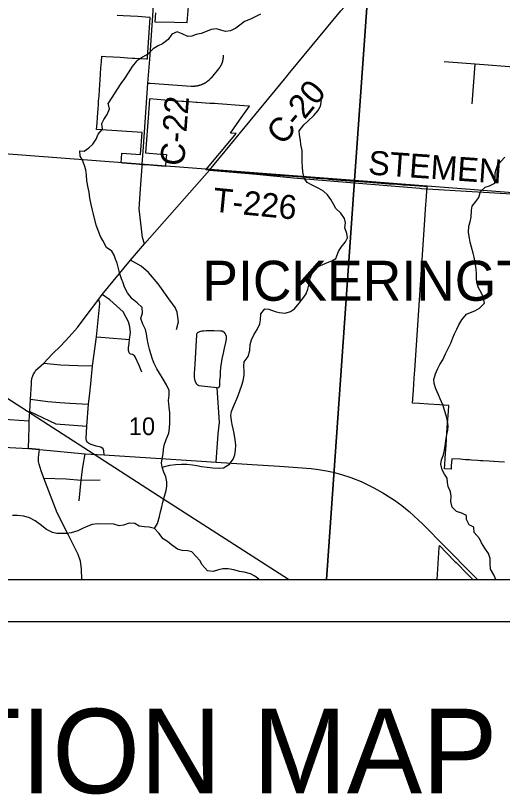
# Model space of a CAD drawing. Extents: x 0 to 34, y 0 to 22.
# Drawn here: x 5.306 to 6.46, y 13.591 to 15.435 of the extents above; entities that cross this region are included whole.
import ezdxf

# ---------------------------------------------------------------- set-up
doc = ezdxf.new("R2010")
doc.units = 0
for name, color, linetype in [('GM_X_City_Street', 7, 'Continuous'), ('GM_X_Corporation', 7, 'Continuous'), ('GM_X_Corporation_Text', 7, 'Continuous'), ('GM_X_County_Road', 7, 'Continuous'), ('GM_X_County_Road_Text', 7, 'Continuous'), ('GM_X_Minor_River', 7, 'Continuous'), ('GM_X_Rail_Line', 7, 'Continuous'), ('GM_X_Section_Text', 7, 'Continuous'), ('GM_X_State_Route', 7, 'Continuous'), ('GM_X_Township_Road', 7, 'Continuous'), ('GM_X_Township_Road_Text', 7, 'Continuous'), ('SH_Data', 7, 'Continuous'), ('SH_Text', 7, 'Continuous')]:
    doc.layers.add(name, color=color, linetype=linetype)

msp = doc.modelspace()

# ---------------------------------------------------------------- linework, layer by layer
at = {"layer": 'GM_X_City_Street'}
msp.add_line((5.4618, 14.3352), (5.5062, 14.3355), dxfattribs=at)
for points in [[(5.6875, 14.6913), (5.6924, 14.7099), (5.6893, 14.7327), (5.6844, 14.7439), (5.6689, 14.7643), (5.6442, 14.7995), (5.6207, 14.8267), (5.6034, 14.8416), (5.5786, 14.8558)], [(5.4819, 14.5408), (5.4842, 14.563), (5.4887, 14.6054), (5.4977, 14.6741), (5.5058, 14.7528), (5.5035, 14.7636)], [(5.7839, 14.5532), (5.7619, 14.5559), (5.7402, 14.5582), (5.7357, 14.5613), (5.7319, 14.5704), (5.73, 14.578), (5.73, 14.5878), (5.732, 14.6099), (5.7348, 14.6656), (5.7356, 14.6774), (5.736, 14.6808), (5.7364, 14.6831)], [(5.8009, 14.6848), (5.7998, 14.6852), (5.796, 14.6875), (5.7918, 14.6879), (5.777, 14.6883), (5.758, 14.6883), (5.7519, 14.688), (5.7474, 14.6876), (5.7443, 14.6872), (5.7417, 14.6865), (5.739, 14.6846), (5.7364, 14.6831)], [(5.7817, 14.3775), (5.7859, 14.4445), (5.7896, 14.4715), (5.7839, 14.5532), (5.7877, 14.5543), (5.7888, 14.555), (5.79, 14.5592), (5.7904, 14.5706), (5.7916, 14.5808), (5.792, 14.5899), (5.7924, 14.6021), (5.7939, 14.6112), (5.7955, 14.6218), (5.7985, 14.6358), (5.8012, 14.6472), (5.8047, 14.6609), (5.8058, 14.6685), (5.8059, 14.6749), (5.8044, 14.6787), (5.8025, 14.6818), (5.8009, 14.6848)], [(5.3727, 14.612), (5.4122, 14.608), (5.4537, 14.6063), (5.4887, 14.6054)], [(5.479, 14.4229), (5.4766, 14.4246), (5.4741, 14.4284), (5.4735, 14.4337), (5.4753, 14.4628), (5.4791, 14.5146), (5.4819, 14.5408)], [(5.3418, 14.5264), (5.3829, 14.5215), (5.4106, 14.5191)], [(5.4106, 14.5191), (5.4343, 14.5171), (5.4791, 14.5146)], [(5.34, 14.4971), (5.4013, 14.4683), (5.4753, 14.4628)], [(5.1265, 14.4887), (5.1972, 14.4848), (5.3384, 14.4755)], [(5.5161, 14.3948), (5.5155, 14.4041), (5.5136, 14.4094), (5.5085, 14.413), (5.4969, 14.4155), (5.4872, 14.4185), (5.4813, 14.4212), (5.479, 14.4229)], [(5.4564, 14.2863), (5.4618, 14.3352), (5.4656, 14.3659), (5.4707, 14.3975)], [(5.3732, 14.34), (5.4263, 14.3381), (5.4618, 14.3352)]]:
    msp.add_lwpolyline(points, dxfattribs=at)
at = {"layer": 'GM_X_Corporation'}
for points in [[(6.5646, 18.0583), (6.0906, 18.0978), (6.0343, 18.1015), (5.9465, 18.1082), (5.8371, 18.1158), (5.5447, 18.1318), (4.9551, 18.1768), (4.7449, 18.1929), (4.5528, 18.2021), (4.3271, 18.2226), (4.1999, 18.2271), (3.8153, 18.2543), (2.3155, 18.3567), (2.2478, 17.3472), (2.1768, 16.323), (2.2862, 16.3208), (2.366, 16.3159), (2.934, 16.2765), (3.1745, 16.2606), (3.1026, 15.287), (3.0406, 14.4484), (3.0169, 14.1), (8.9, 14.1)], [(3.1743, 16.2612), (3.1023, 15.2875), (3.0404, 14.449), (3.0167, 14.1), (8.9, 14.1)], [(3.1743, 16.2612), (3.1023, 15.2875), (3.0404, 14.449), (3.0167, 14.1), (8.1011, 14.1)], [(5.6376, 15.4413), (5.6361, 15.4203), (5.6828, 15.4193), (5.7131, 15.4186), (5.7164, 15.4659)], [(6.4646, 14.3773), (6.4514, 14.3781), (6.4394, 14.3789), (6.4286, 14.3797), (6.4136, 14.3807), (6.4079, 14.381), (6.4019, 14.3814), (6.3866, 14.3825), (6.382, 14.3828), (6.372, 14.3834), (6.3595, 14.3843), (6.3397, 14.3856), (6.3386, 14.3688), (6.3382, 14.3631), (6.3381, 14.3618), (6.338, 14.3607), (6.3224, 14.3617), (6.3233, 14.3717), (6.3244, 14.3866), (6.3252, 14.3984), (6.3264, 14.4167), (6.3274, 14.4318), (6.3284, 14.4475), (6.3299, 14.47), (6.3317, 14.4978), (6.3327, 14.5117), (6.3103, 14.5132), (6.2843, 14.5149), (6.2635, 14.5163), (6.2469, 14.5174), (6.2476, 14.5278), (6.2489, 14.5477), (6.2508, 14.5765), (6.2521, 14.5956), (6.277, 14.9633), (6.2778, 14.9765), (6.2798, 15.0064), (6.2812, 15.0294), (6.2651, 15.0306), (6.2636, 15.0307), (6.24, 15.0325), (6.2393, 15.0325), (6.2248, 15.0336), (6.211, 15.0346), (6.2105, 15.0346), (6.1909, 15.0361), (6.181, 15.0368), (6.1542, 15.0387), (6.153, 15.0388), (6.1516, 15.0389), (6.1459, 15.0394), (6.1081, 15.0421), (6.0564, 15.0463), (6.0488, 15.0469), (6.0451, 15.0472), (6.0186, 15.0493), (5.9943, 15.0512), (5.9627, 15.0537), (5.9047, 15.0581), (5.8952, 15.0589), (5.8941, 15.0589), (5.8513, 15.0623), (5.8211, 15.0648), (5.7826, 15.0678), (5.7708, 15.0688), (5.7697, 15.0689), (5.764, 15.0693), (5.7629, 15.0694), (5.757, 15.0699), (5.8177, 15.1423), (5.8288, 15.1555), (5.8154, 15.1565), (5.8368, 15.1869), (5.8603, 15.2202), (5.847, 15.2211), (5.7859, 15.2257), (5.7778, 15.2263), (5.7665, 15.227), (5.7365, 15.2291), (5.7341, 15.2293), (5.7178, 15.2304), (5.7133, 15.2307), (5.7047, 15.2313), (5.6997, 15.2316), (5.6778, 15.2333), (5.6232, 15.2374), (5.6215, 15.2139), (5.6209, 15.2059), (5.6209, 15.2049), (5.6208, 15.2032), (5.6186, 15.1721), (5.6164, 15.1409), (5.6141, 15.1097), (5.6497, 15.1069), (5.6634, 15.1058), (5.6624, 15.0926), (5.6613, 15.0775), (5.6149, 15.0812), (5.6065, 15.0818), (5.5997, 15.0824), (5.584, 15.0837), (5.5805, 15.084), (5.5592, 15.0858), (5.5565, 15.0861), (5.5581, 15.1087), (5.5581, 15.1093), (5.6025, 15.1059), (5.6062, 15.1584), (5.4981, 15.1648), (5.4992, 15.1799), (5.5002, 15.1941), (5.5016, 15.2149), (5.5022, 15.2228), (5.5029, 15.2325), (5.5038, 15.245), (5.5048, 15.2592), (5.5073, 15.2954), (5.5075, 15.2971), (5.5085, 15.3113), (5.509, 15.319), (5.5095, 15.3255), (5.5104, 15.3387), (5.5203, 15.3381), (5.5373, 15.3371), (5.5543, 15.3361), (5.5713, 15.3351), (5.5831, 15.3344), (5.5883, 15.3341), (5.6161, 15.3325), (5.6185, 15.3324), (5.6187, 15.3358), (5.6254, 15.4305), (5.6231, 15.4306), (5.5955, 15.4323), (5.5785, 15.4333), (5.5614, 15.4344), (5.5471, 15.4352)], [(4.03, 14.1), (6.3052, 14.1), (6.3101, 14.1753), (6.3104, 14.1799), (6.3465, 14.1433), (6.35, 14.1398), (6.3768, 14.1125), (6.3823, 14.107), (6.384, 14.1052), (6.3894, 14.1), (6.567, 14.1)]]:
    msp.add_lwpolyline(points, dxfattribs=at)
for points in [[(5.1682, 16.119), (5.1838, 16.1166), (5.682, 16.08), (6.1806, 16.0412), (6.1096, 15.0446), (5.1019, 15.1206)], [(6.1806, 16.0412), (6.6929, 16.0021), (7.2018, 15.9686), (7.1441, 14.9641), (6.1096, 15.0446)], [(5.0348, 14.1), (6.0432, 14.1), (6.1096, 15.0446), (5.1019, 15.1206)], [(6.0432, 14.1), (7.0881, 14.1), (7.1441, 14.9641), (6.1096, 15.0446)]]:
    msp.add_lwpolyline(points, close=True, dxfattribs=at)
at = {"layer": 'GM_X_County_Road'}
for p, q in [((5.3364, 14.4096), (5.338, 14.4603)), ((5.3625, 14.4075), (5.3364, 14.4096))]:
    msp.add_line(p, q, dxfattribs=at)
for points in [[(5.7654, 15.0689), (5.9431, 15.2845), (5.9472, 15.2891), (5.956, 15.2997), (6.0772, 15.4457), (6.0779, 15.4466), (6.0901, 15.461), (6.1222, 15.4992), (6.1287, 15.5069), (6.1349, 15.5146), (6.2818, 15.6943), (6.3195, 15.7413)], [(5.6061, 15.0833), (5.609, 15.1242), (5.6198, 15.2751), (5.625, 15.3412), (5.6348, 15.4828)], [(5.338, 14.4603), (5.3384, 14.4755), (5.34, 14.4971), (5.3418, 14.5264), (5.3439, 14.5631), (5.3438, 14.5688), (5.3446, 14.5753), (5.3467, 14.5817), (5.3478, 14.584), (5.3517, 14.5904), (5.354, 14.595), (5.3727, 14.612), (5.3926, 14.6336), (5.4136, 14.6529), (5.4334, 14.6741), (5.4526, 14.6964), (5.4713, 14.7207), (5.5035, 14.7636), (5.511, 14.7748), (5.5786, 14.8558), (5.6114, 14.8948), (5.7654, 15.0689)], [(5.6114, 14.8948), (5.6065, 14.9095), (5.5992, 14.9771), (5.6025, 15.0244), (5.6057, 15.0774), (5.6061, 15.0833)], [(5.367, 14.3573), (5.3616, 14.3727), (5.3606, 14.3792), (5.3606, 14.3886), (5.3625, 14.4075)], [(5.4306, 14.2066), (5.4048, 14.2577), (5.3732, 14.34), (5.367, 14.3573)], [(5.4628, 14.1), (5.4621, 14.1249), (5.46, 14.1428), (5.4544, 14.1586), (5.437, 14.1939), (5.4306, 14.2066)]]:
    msp.add_lwpolyline(points, dxfattribs=at)
at = {"layer": 'GM_X_Minor_River'}
for points in [[(5.8861, 15.4379), (5.8735, 15.4316), (5.8625, 15.4264), (5.8488, 15.4212), (5.8373, 15.4118), (5.8278, 15.4047), (5.8156, 15.3984), (5.8038, 15.3974), (5.7921, 15.4002), (5.7823, 15.4033), (5.7694, 15.4015), (5.7565, 15.3964), (5.7462, 15.3927), (5.7344, 15.3898), (5.7238, 15.3865), (5.7143, 15.385), (5.7007, 15.3916), (5.6887, 15.3967), (5.6761, 15.3911), (5.6673, 15.3783), (5.6539, 15.3682), (5.6436, 15.3634), (5.6318, 15.3559), (5.6195, 15.3435), (5.607, 15.3361), (5.5925, 15.3271), (5.5821, 15.3139), (5.5728, 15.2992), (5.5644, 15.286), (5.5555, 15.274), (5.5258, 15.2274)], [(5.6533, 14.3655), (5.6716, 14.3707), (5.6852, 14.372), (5.6992, 14.3726), (5.7117, 14.3725), (5.7254, 14.3712), (5.736, 14.3696), (5.7469, 14.3676), (5.7602, 14.3656), (5.7734, 14.3643), (5.7863, 14.3634), (5.7992, 14.364), (5.8129, 14.373), (5.8217, 14.3843), (5.826, 14.3952), (5.8276, 14.4058), (5.8278, 14.4184), (5.8264, 14.4301), (5.8243, 14.4457), (5.8221, 14.4568), (5.8196, 14.467), (5.8174, 14.4765), (5.816, 14.4879), (5.818, 14.4978), (5.8223, 14.5095), (5.8324, 14.5329), (5.8375, 14.5462), (5.8422, 14.5602), (5.8457, 14.5704), (5.8481, 14.5836), (5.8478, 14.5935), (5.8468, 14.6045), (5.8481, 14.6147), (5.8573, 14.6279), (5.8612, 14.6423), (5.8622, 14.656), (5.8649, 14.6669), (5.8704, 14.679), (5.8788, 14.6918), (5.885, 14.7051), (5.8867, 14.7149), (5.8876, 14.7289), (5.8964, 14.7402), (5.9066, 14.7401), (5.9209, 14.7343), (5.9308, 14.7315), (5.9452, 14.7306), (5.9573, 14.7343), (5.9669, 14.7403), (5.978, 14.7542), (5.9872, 14.7647), (5.9945, 14.7764), (5.9988, 14.7874), (6.002, 14.7995), (6.0032, 14.8105), (6.0087, 14.8256), (6.0148, 14.8354), (6.0248, 14.8418), (6.0343, 14.8458), (6.0453, 14.8499), (6.0552, 14.854), (6.0647, 14.8599), (6.0714, 14.8766), (6.0775, 14.8867), (6.0879, 14.8988), (6.0925, 14.9086), (6.0911, 14.9192), (6.0867, 14.9322), (6.0876, 14.9439), (6.0858, 14.9542), (6.0769, 14.9668), (6.0653, 14.9783), (6.0593, 14.9883), (6.0534, 14.9997), (6.0451, 15.0104), (6.0354, 15.0189), (6.0249, 15.0258), (6.009, 15.0332), (5.997, 15.0398), (5.9903, 15.0497), (5.987, 15.0653), (5.986, 15.0771), (5.9854, 15.0881), (5.9855, 15.1021), (5.9849, 15.1154), (5.9824, 15.1299), (5.981, 15.1394), (5.9789, 15.1527), (5.9782, 15.1622), (5.989, 15.1761), (5.9985, 15.1847), (6.0127, 15.1986), (6.0227, 15.2091), (6.0288, 15.2205), (6.0313, 15.2341)], [(5.5338, 14.8772), (5.5213, 14.8859), (5.5132, 14.9023), (5.5077, 14.9119), (5.5033, 14.9222), (5.4967, 14.9386), (5.4907, 14.9645), (5.4885, 14.974), (5.4853, 14.9877), (5.4821, 15.0029), (5.4801, 15.0166), (5.4779, 15.0269), (5.4751, 15.0436), (5.4738, 15.0573), (5.4725, 15.0695), (5.4692, 15.0802), (5.4649, 15.0927), (5.459, 15.1023), (5.4587, 15.1145), (5.4686, 15.1136), (5.4793, 15.1218), (5.4889, 15.1304), (5.497, 15.1424), (5.5021, 15.1537), (5.5117, 15.1657), (5.5104, 15.179), (5.5154, 15.1892), (5.5228, 15.2005), (5.5283, 15.2137), (5.5258, 15.2274)], [(6.4442, 14.1), (6.4396, 14.1107), (6.4318, 14.1244), (6.4305, 14.1381), (6.431, 14.1495), (6.4269, 14.1613), (6.4184, 14.1743), (6.4102, 14.1865), (6.4053, 14.1972), (6.393, 14.211), (6.392, 14.2239), (6.3807, 14.2289), (6.3748, 14.2415), (6.3749, 14.251), (6.3632, 14.2568), (6.3507, 14.2607), (6.3406, 14.2711), (6.3377, 14.2844), (6.3386, 14.2973), (6.3365, 14.3076), (6.3309, 14.3201), (6.3299, 14.3296), (6.3288, 14.3395), (6.3229, 14.3495), (6.3166, 14.359), (6.3141, 14.3731), (6.3157, 14.3829), (6.3203, 14.3946), (6.3227, 14.406), (6.324, 14.4166), (6.3253, 14.428), (6.3284, 14.4431), (6.3301, 14.453), (6.3309, 14.4632), (6.3299, 14.475), (6.3274, 14.4857), (6.3186, 14.5131), (6.3123, 14.5272), (6.3086, 14.5367), (6.3016, 14.5508), (6.2979, 14.5634), (6.2973, 14.5736), (6.3012, 14.5869), (6.3062, 14.5975), (6.3117, 14.6084), (6.3186, 14.6201), (6.3252, 14.6344), (6.3314, 14.6465), (6.3372, 14.659), (6.3423, 14.6718), (6.3465, 14.6817), (6.3516, 14.6922), (6.3566, 14.7024), (6.3639, 14.7145), (6.3743, 14.7281), (6.3842, 14.7317), (6.3941, 14.7358), (6.4055, 14.7425), (6.417, 14.7542), (6.4142, 14.769), (6.4097, 14.7789), (6.4034, 14.79), (6.3994, 14.8026), (6.3987, 14.8132), (6.3985, 14.8238), (6.3978, 14.8348), (6.396, 14.8459), (6.3932, 14.8626), (6.3906, 14.8725), (6.3866, 14.8862), (6.3834, 14.8984), (6.3816, 14.9079), (6.3791, 14.9216), (6.3803, 14.936), (6.3831, 14.9466), (6.3855, 14.9575), (6.3868, 14.9738), (6.3881, 14.9837), (6.3969, 14.9946), (6.4042, 15.0044), (6.4081, 15.018), (6.4185, 15.0289), (6.4291, 15.0315), (6.4421, 15.0378), (6.4429, 15.0492), (6.4423, 15.0628), (6.4474, 15.078), (6.4562, 15.0896), (6.4654, 15.0994)], [(5.6355, 14.2207), (5.6428, 14.2324), (5.6468, 14.2491), (5.6495, 14.2601), (5.6523, 14.2718), (5.6551, 14.2828), (5.659, 14.2968), (5.6626, 14.3108), (5.6642, 14.3206), (5.6643, 14.3309), (5.6618, 14.3427), (5.6577, 14.3537), (5.6533, 14.3655), (5.6519, 14.375), (5.6532, 14.3853), (5.6556, 14.397), (5.6564, 14.4073), (5.6584, 14.4175), (5.6631, 14.4311), (5.6693, 14.4462), (5.671, 14.4583), (5.6715, 14.4701), (5.6717, 14.4841), (5.6714, 14.4944), (5.67, 14.5077), (5.6687, 14.5236), (5.6699, 14.5358), (5.6701, 14.5471), (5.6638, 14.5609), (5.656, 14.5742), (5.6474, 14.588), (5.6407, 14.5987), (5.6348, 14.6109), (5.6303, 14.6212), (5.6263, 14.6341), (5.6234, 14.6448), (5.6205, 14.6577), (5.618, 14.6707), (5.6162, 14.6813), (5.6137, 14.6916), (5.6077, 14.7045), (5.6026, 14.7179), (5.6065, 14.7311), (5.6059, 14.744), (5.5939, 14.7548), (5.5826, 14.764), (5.571, 14.7785), (5.5643, 14.7915), (5.5607, 14.8022), (5.557, 14.8117), (5.5529, 14.8231), (5.5501, 14.8364), (5.5468, 14.8486), (5.5431, 14.8582), (5.5398, 14.8677), (5.5338, 14.8772)], [(5.539, 14.2309), (5.5007, 14.2315), (5.4874, 14.2298), (5.4733, 14.2247), (5.4634, 14.2199), (5.4535, 14.2147), (5.4379, 14.21), (5.4277, 14.2086), (5.4148, 14.2084), (5.4042, 14.2089), (5.3933, 14.211), (5.379, 14.218), (5.364, 14.2296), (5.3528, 14.2385), (5.3393, 14.2459), (5.3257, 14.2498), (5.3106, 14.2516), (5.2989, 14.2514)], [(5.8827, 14.1009), (5.8729, 14.1075), (5.8627, 14.1133), (5.848, 14.1168), (5.8367, 14.1185), (5.8235, 14.1228), (5.8102, 14.1252), (5.7973, 14.1249), (5.7871, 14.1228), (5.7742, 14.1184), (5.7605, 14.12), (5.7482, 14.1346), (5.7426, 14.1449), (5.7344, 14.1544), (5.7239, 14.1652), (5.7141, 14.1679), (5.7012, 14.1681), (5.6895, 14.1712), (5.6756, 14.1816), (5.6658, 14.1901), (5.6561, 14.1962), (5.6456, 14.2093), (5.6355, 14.2207), (5.6226, 14.2239), (5.6117, 14.2244), (5.5992, 14.2264), (5.589, 14.2322), (5.575, 14.2328), (5.5621, 14.228), (5.5518, 14.2266), (5.539, 14.2309)]]:
    msp.add_lwpolyline(points, dxfattribs=at)
at = {"layer": 'GM_X_Rail_Line'}
msp.add_lwpolyline([(5.9528, 14.1), (5.6437, 14.2982), (5.4789, 14.4041), (4.8128, 14.8326), (4.5194, 15.0215), (4.222, 15.2127), (4.0411, 15.3289), (3.919, 15.4076), (3.8544, 15.4493), (3.8245, 15.4671), (3.7478, 15.5086), (3.3032, 15.7468), (3.1426, 15.8323)], dxfattribs=at)
at = {"layer": 'GM_X_State_Route'}
msp.add_line((5.3364, 14.4096), (5.3625, 14.4075), dxfattribs=at)
for points in [[(5.2553, 14.4147), (5.2614, 14.4142), (5.3364, 14.4096)], [(5.3625, 14.4075), (5.4707, 14.3975), (5.4997, 14.3958)], [(5.4997, 14.3958), (5.5161, 14.3948), (5.626, 14.3876)], [(5.626, 14.3876), (5.7466, 14.3798), (5.7817, 14.3775), (5.8666, 14.3722), (5.9317, 14.3682), (6.0069, 14.3624), (6.024, 14.3604), (6.0432, 14.357), (6.0589, 14.3536), (6.0783, 14.3485), (6.1003, 14.3411), (6.1252, 14.3314), (6.1554, 14.3169), (6.1767, 14.3047), (6.2043, 14.2878), (6.2218, 14.275), (6.2391, 14.2609), (6.2712, 14.2311), (6.3251, 14.1763), (6.3889, 14.1115), (6.3969, 14.1039), (6.4011, 14.1)]]:
    msp.add_lwpolyline(points, dxfattribs=at)
at = {"layer": 'GM_X_Township_Road'}
msp.add_line((6.3881, 15.2259), (6.3948, 15.3196), dxfattribs=at)
for points in [[(5.6198, 15.2751), (5.6254, 15.2747), (5.7225, 15.2681), (5.7233, 15.268), (5.724, 15.268), (5.7248, 15.268), (5.7255, 15.268), (5.7263, 15.2679), (5.727, 15.2679), (5.7278, 15.268), (5.7286, 15.268), (5.7293, 15.268), (5.7301, 15.2681), (5.7308, 15.2681), (5.7316, 15.2682), (5.7323, 15.2682), (5.7331, 15.2683), (5.7338, 15.2684), (5.7346, 15.2685), (5.7353, 15.2686), (5.7361, 15.2688), (5.7368, 15.2689), (5.7376, 15.269), (5.7383, 15.2692), (5.7391, 15.2693), (5.7398, 15.2695), (5.7405, 15.2697), (5.7413, 15.2699), (5.742, 15.2701), (5.7427, 15.2703), (5.7435, 15.2705), (5.7442, 15.2707), (5.7449, 15.271), (5.7456, 15.2712), (5.7463, 15.2715), (5.747, 15.2717), (5.7477, 15.272), (5.7484, 15.2723), (5.7491, 15.2726), (5.7498, 15.2729), (5.7505, 15.2732), (5.7512, 15.2735), (5.7519, 15.2738), (5.7526, 15.2742), (5.7533, 15.2745), (5.7539, 15.2749), (5.7546, 15.2753), (5.7552, 15.2756), (5.7559, 15.276), (5.7565, 15.2764), (5.7572, 15.2768), (5.7578, 15.2772), (5.7585, 15.2776), (5.7591, 15.278), (5.7597, 15.2785), (5.7603, 15.2789), (5.7609, 15.2794), (5.7615, 15.2798), (5.7621, 15.2803), (5.7627, 15.2808), (5.7633, 15.2812), (5.7639, 15.2817), (5.7645, 15.2822), (5.765, 15.2827), (5.7656, 15.2832), (5.7662, 15.2837), (5.7667, 15.2843), (5.7672, 15.2848), (5.7678, 15.2853), (5.7683, 15.2859), (5.7688, 15.2864), (5.7693, 15.287), (5.7698, 15.2876), (5.7703, 15.2881), (5.7708, 15.2886), (5.7877, 15.3088), (5.7882, 15.3094), (5.7886, 15.31), (5.7891, 15.3106), (5.7895, 15.3112), (5.79, 15.3118), (5.7904, 15.3125), (5.7908, 15.3131), (5.7913, 15.3137), (5.7917, 15.3144), (5.792, 15.315), (5.7924, 15.3157), (5.7928, 15.3163), (5.7932, 15.317), (5.7935, 15.3177), (5.7939, 15.3183), (5.7942, 15.319), (5.7945, 15.3197), (5.7948, 15.3204), (5.7951, 15.3211), (5.7954, 15.3218), (5.7957, 15.3225), (5.7959, 15.3232), (5.7962, 15.3239), (5.7964, 15.3247), (5.7966, 15.3254), (5.7969, 15.3261), (5.7971, 15.3268), (5.7972, 15.3276), (5.7974, 15.3283), (5.7976, 15.329), (5.7978, 15.3298), (5.7979, 15.3305), (5.798, 15.3313), (5.7982, 15.332), (5.7983, 15.3328), (5.7984, 15.3335), (5.7984, 15.3343), (5.7985, 15.335), (5.7986, 15.3358), (5.7986, 15.3365), (5.7987, 15.3373), (5.7987, 15.338), (5.7987, 15.3388), (5.7987, 15.3396), (5.7987, 15.3408)], [(6.5351, 15.0096), (6.5427, 15.1255), (6.5462, 15.1724), (6.5467, 15.1827), (6.5511, 15.1981), (6.561, 15.2179), (6.5674, 15.2274), (6.5702, 15.2334), (6.5736, 15.245), (6.5745, 15.258), (6.5719, 15.273), (6.5637, 15.2886), (6.5552, 15.2971), (6.5399, 15.3062), (6.5255, 15.3101), (6.4972, 15.3121), (6.3948, 15.3196), (6.3218, 15.325)], [(5.7654, 15.0689), (5.8774, 15.0592), (5.9646, 15.0507), (6.2643, 15.0259), (6.2683, 15.0257)], [(6.2683, 15.0257), (6.5351, 15.0096), (6.722, 14.9963), (7.1458, 14.9647)], [(5.6053, 14.5906), (5.5993, 14.6063), (5.5902, 14.6253), (5.5876, 14.6292), (5.5833, 14.6321), (5.5787, 14.6336), (5.5755, 14.6364), (5.5735, 14.6417), (5.5734, 14.6484), (5.5753, 14.6588), (5.576, 14.6682), (5.5781, 14.6848), (5.5772, 14.6982), (5.5738, 14.7094), (5.5685, 14.7204), (5.5612, 14.7335), (5.5294, 14.7622), (5.511, 14.7748)], [(5.4977, 14.6741), (5.5181, 14.6729), (5.576, 14.6682)]]:
    msp.add_lwpolyline(points, dxfattribs=at)
at = {"layer": 'SH_Data'}
for p, q in [((2.1, 14.1), (8.9, 14.1)), ((2, 14), (9, 14))]:
    msp.add_line(p, q, dxfattribs=at)

# ---------------------------------------------------------------- texts
at = {"layer": 'GM_X_Corporation_Text'}
msp.add_text('PICKERINGTON', height=0.094697, rotation=0, dxfattribs=at).set_placement((5.7487, 14.7597))
at = {"layer": 'GM_X_County_Road_Text'}
for s, rotation, p in [('C-20', 50.3717, (5.9396, 15.1253)), ('C-22', 85.8896, (5.7054, 15.0778))]:
    msp.add_text(s, height=0.05682, rotation=rotation, dxfattribs=at).set_placement(p)
at = {"layer": 'GM_X_Section_Text'}
msp.add_text('10', height=0.04186, rotation=0, dxfattribs=at).set_placement((5.5744, 14.4416))
at = {"layer": 'GM_X_Township_Road_Text'}
for s, rotation, p in [('STEMEN', 356.0093, (6.1406, 15.0588)), ('T-226', 354.4014, (5.7718, 14.971))]:
    msp.add_text(s, height=0.05682, rotation=rotation, dxfattribs=at).set_placement(p)
at = {"layer": 'SH_Text'}
msp.add_text('LOCATION MAP', height=0.2, dxfattribs=at).set_placement((4.4269, 13.5938))

doc.saveas('drawing.dxf')
